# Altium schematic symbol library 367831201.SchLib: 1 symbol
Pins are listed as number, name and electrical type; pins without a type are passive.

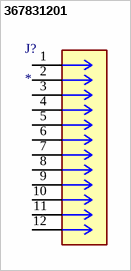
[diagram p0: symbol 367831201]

## 367831201
designator J?
MP: 367831201
footprint CONN_3678312XX_MOL
pins: 1, 2, 3, 4, 5, 6, 7, 8, 9, 10, 11, 12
